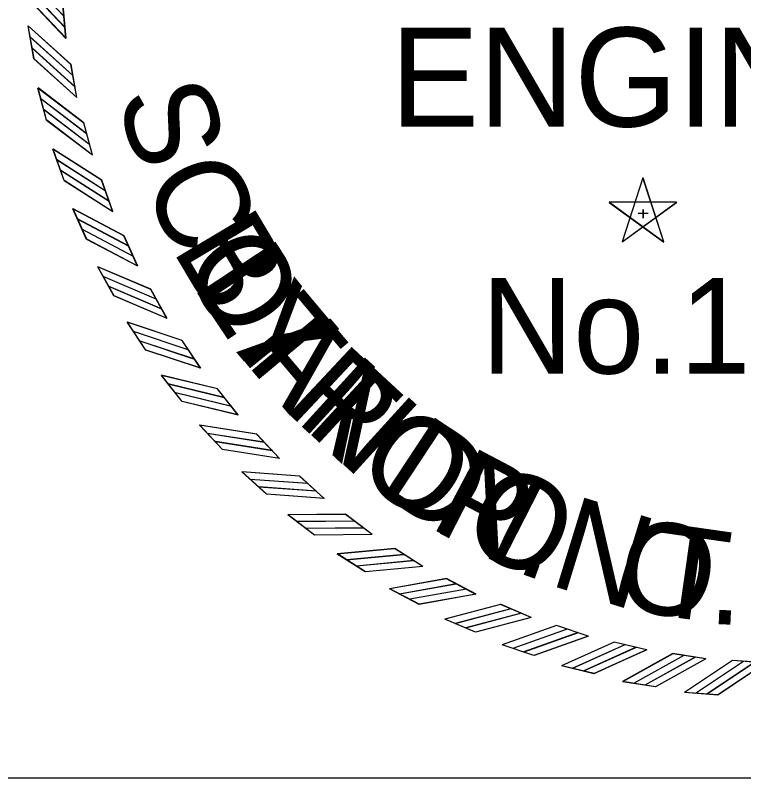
# Model space of a CAD drawing. Extents: x 0 to 1228740, y 0 to 152440.
# Drawn here: x 30.801 to 31.99, y 17.405 to 18.649 of the extents above; entities that cross this region are included whole.
import ezdxf

# ---------------------------------------------------------------- set-up
doc = ezdxf.new("R2010")
doc.units = 0
for name, color, linetype in [('R_No Plot', 7, 'Continuous'), ('STAMP_BOL', 7, 'Continuous'), ('STAMP_LKM', 7, 'Continuous'), ('STAMP_SPT', 7, 'Continuous')]:
    doc.layers.add(name, color=color, linetype=linetype)

msp = doc.modelspace()

# ---------------------------------------------------------------- linework, layer by layer
at = {"layer": 'R_No Plot'}
msp.add_lwpolyline([(30.6665, 20.1432), (30.6665, 17.4052), (33.4231, 17.4052)], dxfattribs=at)
msp.add_lwpolyline([(30.6665, 20.1432), (30.6665, 17.4052), (33.4231, 17.4052)], dxfattribs=at)
at = {"layer": 'STAMP_BOL'}
for p, q in [((30.8835, 18.6116), (30.8785, 18.6659)), ((30.8312, 18.5784), (30.8218, 18.632)), ((30.9012, 18.5153), (30.8917, 18.569)), ((30.8518, 18.4779), (30.8379, 18.5305)), ((30.9267, 18.4208), (30.9128, 18.4736)), ((30.8805, 18.3795), (30.8624, 18.4308)), ((30.9599, 18.3288), (30.9417, 18.3802)), ((31.8254, 18.3839), (31.7914, 18.2794)), ((31.8594, 18.2795), (31.8255, 18.384)), ((31.8803, 18.344), (31.7705, 18.3441)), ((31.7706, 18.344), (31.8594, 18.2793)), ((31.7915, 18.2795), (31.8804, 18.344)), ((30.9173, 18.2837), (30.895, 18.3333)), ((31.8176, 18.3264), (31.8339, 18.3264)), ((31.8255, 18.3323), (31.8255, 18.3185)), ((31.0006, 18.2397), (30.9782, 18.2895)), ((30.9619, 18.1913), (30.9356, 18.2389)), ((31.0485, 18.1544), (31.0221, 18.2021)), ((31.014, 18.103), (30.9838, 18.1482)), ((31.1033, 18.0733), (31.0731, 18.1187)), ((31.0731, 18.0192), (31.0393, 18.0618)), ((31.1647, 17.997), (31.1308, 18.0397)), ((31.139, 17.9406), (31.1018, 17.9803)), ((31.2321, 17.926), (31.1948, 17.9658)), ((31.2112, 17.8677), (31.1708, 17.9042)), ((31.3051, 17.8609), (31.2646, 17.8974)), ((31.2891, 17.801), (31.2459, 17.834)), ((31.3833, 17.8019), (31.3399, 17.835)), ((31.466, 17.7497), (31.4201, 17.7791)), ((31.3723, 17.741), (31.3265, 17.7703)), ((31.5528, 17.7044), (31.5046, 17.73)), ((31.4601, 17.688), (31.412, 17.7135)), ((31.6431, 17.6665), (31.5929, 17.688)), ((31.552, 17.6425), (31.502, 17.6639)), ((31.7361, 17.6362), (31.6844, 17.6534)), ((31.6474, 17.6047), (31.5958, 17.6219)), ((31.8314, 17.6137), (31.7784, 17.6266)), ((31.9282, 17.599), (31.8743, 17.6075)), ((32.0259, 17.5925), (31.9715, 17.5965)), ((31.7456, 17.575), (31.6927, 17.5878)), ((31.8458, 17.5534), (31.7921, 17.5619)), ((31.9475, 17.5402), (31.8933, 17.5442))]:
    msp.add_line(p, q, dxfattribs=at)
for points in [[(30.88, 18.6478), (30.8155, 18.7164)], [(30.8822, 18.629), (30.8177, 18.6976)], [(30.8836, 18.6116), (30.8191, 18.6802)], [(30.8917, 18.569), (30.8217, 18.632)], [(30.8946, 18.5511), (30.8247, 18.6141)], [(30.8983, 18.5325), (30.8284, 18.5956)], [(30.9012, 18.5153), (30.8313, 18.5783)], [(30.9128, 18.4735), (30.8379, 18.5306)], [(30.9172, 18.4559), (30.8423, 18.513)], [(30.9224, 18.4378), (30.8476, 18.4948)], [(30.9267, 18.4208), (30.8518, 18.4778)], [(30.9417, 18.3801), (30.8624, 18.4308)], [(30.9476, 18.363), (30.8682, 18.4136)], [(30.9543, 18.3453), (30.8749, 18.396)], [(30.96, 18.3287), (30.8806, 18.3794)], [(30.9782, 18.2894), (30.895, 18.3334)], [(30.9855, 18.2728), (30.9023, 18.3168)], [(30.9936, 18.2557), (30.9104, 18.2997)], [(31.0007, 18.2397), (30.9174, 18.2837)], [(31.0221, 18.202), (30.9355, 18.239)], [(31.0308, 18.1861), (30.9442, 18.223)], [(31.0403, 18.1698), (30.9537, 18.2067)], [(31.0486, 18.1544), (30.962, 18.1913)], [(31.0731, 18.1186), (30.9837, 18.1483)], [(31.083, 18.1034), (30.9936, 18.1331)], [(31.0938, 18.0879), (31.0045, 18.1176)], [(31.1034, 18.0733), (31.0141, 18.1029)], [(31.1308, 18.0396), (31.0393, 18.0618)], [(31.1419, 18.0253), (31.0504, 18.0475)], [(31.154, 18.0108), (31.0625, 18.033)], [(31.1647, 17.997), (31.0732, 18.0192)], [(31.1948, 17.9657), (31.1018, 17.9803)], [(31.207, 17.9524), (31.114, 17.9669)], [(31.2203, 17.9389), (31.1273, 17.9534)], [(31.2321, 17.926), (31.1391, 17.9406)], [(31.2647, 17.8973), (31.1708, 17.9042)], [(31.278, 17.8851), (31.1841, 17.8919)], [(31.2923, 17.8727), (31.1984, 17.8795)], [(31.3052, 17.8608), (31.2113, 17.8677)], [(31.34, 17.835), (31.2458, 17.834)], [(31.3543, 17.8238), (31.2601, 17.8229)], [(31.3695, 17.8127), (31.2754, 17.8117)], [(31.3834, 17.8019), (31.2892, 17.801)], [(31.4201, 17.779), (31.3264, 17.7703)], [(31.4353, 17.7691), (31.3416, 17.7604)], [(31.4515, 17.7593), (31.3577, 17.7505)], [(31.4661, 17.7497), (31.3724, 17.741)], [(31.5047, 17.7299), (31.412, 17.7135)], [(31.5206, 17.7213), (31.4279, 17.7048)], [(31.5375, 17.7128), (31.4448, 17.6964)], [(31.5529, 17.7045), (31.4602, 17.688)], [(31.593, 17.6879), (31.502, 17.6639)], [(31.6096, 17.6806), (31.5186, 17.6566)], [(31.6271, 17.6736), (31.5361, 17.6495)], [(31.6432, 17.6666), (31.5521, 17.6425)], [(31.6845, 17.6534), (31.5957, 17.6219)], [(31.7016, 17.6475), (31.6129, 17.616)], [(31.7197, 17.6419), (31.6309, 17.6104)], [(31.7362, 17.6362), (31.6475, 17.6047)], [(31.7785, 17.6265), (31.6926, 17.5878)], [(31.796, 17.622), (31.7102, 17.5834)], [(31.8145, 17.618), (31.7287, 17.5793)], [(31.8315, 17.6137), (31.7456, 17.575)], [(31.8744, 17.6075), (31.792, 17.5618)], [(31.8923, 17.6045), (31.8099, 17.5588)], [(31.911, 17.602), (31.8286, 17.5563)], [(31.9283, 17.5991), (31.8459, 17.5534)], [(31.9715, 17.5964), (31.8932, 17.5442)], [(31.9896, 17.5949), (31.9113, 17.5427)], [(32.0085, 17.594), (31.9302, 17.5417)], [(32.0259, 17.5925), (31.9476, 17.5402)]]:
    msp.add_lwpolyline(points, dxfattribs=at)
at = {"layer": 'STAMP_LKM'}
for p, q in [((30.8838, 18.6117), (30.8788, 18.666)), ((30.8315, 18.5785), (30.822, 18.6321)), ((30.9014, 18.5154), (30.8919, 18.5691)), ((30.852, 18.478), (30.8382, 18.5306)), ((30.9269, 18.4209), (30.913, 18.4737)), ((30.8808, 18.3796), (30.8626, 18.4309)), ((30.9601, 18.3289), (30.9419, 18.3803)), ((31.8256, 18.384), (31.7915, 18.2795)), ((31.8595, 18.2796), (31.8257, 18.3841)), ((31.8805, 18.3441), (31.7706, 18.3442)), ((31.7707, 18.3441), (31.8595, 18.2795)), ((31.7917, 18.2796), (31.8806, 18.3441)), ((30.9176, 18.2838), (30.8953, 18.3335)), ((31.8178, 18.3266), (31.8341, 18.3266)), ((31.8257, 18.3324), (31.8257, 18.3186)), ((31.0008, 18.2399), (30.9785, 18.2896)), ((30.9621, 18.1915), (30.9358, 18.2391)), ((31.0487, 18.1545), (31.0223, 18.2022)), ((31.0142, 18.1031), (30.984, 18.1484)), ((31.1035, 18.0734), (31.0733, 18.1188)), ((31.0734, 18.0193), (31.0395, 18.0619)), ((31.1649, 17.9971), (31.131, 18.0399)), ((31.1392, 17.9407), (31.102, 17.9804)), ((31.2323, 17.9262), (31.195, 17.9659)), ((31.2114, 17.8678), (31.171, 17.9043)), ((31.3053, 17.861), (31.2648, 17.8976)), ((31.2893, 17.8012), (31.2461, 17.8342)), ((31.3835, 17.8021), (31.3401, 17.8352)), ((31.4662, 17.7499), (31.4203, 17.7793)), ((31.3725, 17.7411), (31.3267, 17.7705)), ((31.553, 17.7046), (31.5048, 17.7301)), ((31.4603, 17.6882), (31.4122, 17.7136)), ((31.6432, 17.6667), (31.5931, 17.6881)), ((31.5522, 17.6427), (31.5022, 17.6641)), ((31.7363, 17.6364), (31.6846, 17.6536)), ((31.6476, 17.6049), (31.5959, 17.6221)), ((31.8315, 17.6138), (31.7786, 17.6267)), ((31.9283, 17.5992), (31.8745, 17.6077)), ((32.026, 17.5927), (31.9716, 17.5967)), ((31.7457, 17.5751), (31.6929, 17.588)), ((31.846, 17.5536), (31.7922, 17.562)), ((31.9477, 17.5404), (31.8934, 17.5444))]:
    msp.add_line(p, q, dxfattribs=at)
for points in [[(30.8802, 18.6479), (30.8158, 18.7165)], [(30.8824, 18.6291), (30.8179, 18.6977)], [(30.8838, 18.6116), (30.8194, 18.6803)], [(30.8919, 18.5691), (30.822, 18.6321)], [(30.8949, 18.5512), (30.825, 18.6142)], [(30.8986, 18.5326), (30.8287, 18.5957)], [(30.9014, 18.5154), (30.8315, 18.5784)], [(30.913, 18.4736), (30.8381, 18.5307)], [(30.9174, 18.456), (30.8426, 18.5131)], [(30.9227, 18.4379), (30.8478, 18.4949)], [(30.927, 18.4209), (30.8521, 18.4779)], [(30.9419, 18.3802), (30.8626, 18.4309)], [(30.9478, 18.3631), (30.8685, 18.4137)], [(30.9545, 18.3454), (30.8752, 18.3961)], [(30.9602, 18.3288), (30.8808, 18.3795)], [(30.9784, 18.2895), (30.8952, 18.3335)], [(30.9857, 18.2729), (30.9025, 18.3169)], [(30.9939, 18.2559), (30.9106, 18.2998)], [(31.0009, 18.2398), (30.9176, 18.2838)], [(31.0223, 18.2022), (30.9357, 18.2391)], [(31.031, 18.1862), (30.9444, 18.2232)], [(31.0405, 18.1699), (30.9539, 18.2068)], [(31.0488, 18.1545), (30.9622, 18.1914)], [(31.0733, 18.1187), (30.984, 18.1484)], [(31.0832, 18.1036), (30.9939, 18.1332)], [(31.094, 18.0881), (31.0047, 18.1177)], [(31.1036, 18.0734), (31.0143, 18.1031)], [(31.131, 18.0398), (31.0395, 18.062)], [(31.1421, 18.0255), (31.0506, 18.0477)], [(31.1542, 18.0109), (31.0627, 18.0331)], [(31.1649, 17.9971), (31.0734, 18.0193)], [(31.195, 17.9659), (31.102, 17.9804)], [(31.2072, 17.9525), (31.1142, 17.9671)], [(31.2205, 17.939), (31.1275, 17.9536)], [(31.2323, 17.9262), (31.1393, 17.9407)], [(31.2649, 17.8975), (31.171, 17.9043)], [(31.2782, 17.8852), (31.1843, 17.892)], [(31.2925, 17.8729), (31.1986, 17.8797)], [(31.3054, 17.861), (31.2115, 17.8678)], [(31.3401, 17.8351), (31.246, 17.8342)], [(31.3544, 17.824), (31.2603, 17.823)], [(31.3697, 17.8129), (31.2756, 17.8119)], [(31.3835, 17.8021), (31.2894, 17.8011)], [(31.4203, 17.7792), (31.3266, 17.7705)], [(31.4355, 17.7693), (31.3418, 17.7605)], [(31.4516, 17.7594), (31.3579, 17.7507)], [(31.4663, 17.7499), (31.3726, 17.7411)], [(31.5049, 17.7301), (31.4122, 17.7136)], [(31.5208, 17.7214), (31.4281, 17.705)], [(31.5377, 17.713), (31.445, 17.6965)], [(31.5531, 17.7046), (31.4604, 17.6882)], [(31.5932, 17.6881), (31.5021, 17.664)], [(31.6098, 17.6808), (31.5187, 17.6568)], [(31.6273, 17.6738), (31.5363, 17.6497)], [(31.6433, 17.6667), (31.5523, 17.6427)], [(31.6846, 17.6535), (31.5959, 17.6221)], [(31.7018, 17.6477), (31.613, 17.6162)], [(31.7198, 17.6421), (31.6311, 17.6106)], [(31.7364, 17.6364), (31.6477, 17.6049)], [(31.7786, 17.6267), (31.6928, 17.588)], [(31.7962, 17.6222), (31.7104, 17.5835)], [(31.8146, 17.6182), (31.7288, 17.5795)], [(31.8316, 17.6139), (31.7458, 17.5752)], [(31.8745, 17.6077), (31.7922, 17.562)], [(31.8924, 17.6047), (31.8101, 17.559)], [(31.9111, 17.6021), (31.8288, 17.5565)], [(31.9284, 17.5993), (31.8461, 17.5536)], [(31.9717, 17.5966), (31.8934, 17.5443)], [(31.9897, 17.5951), (31.9114, 17.5428)], [(32.0086, 17.5942), (31.9303, 17.5419)], [(32.0261, 17.5927), (31.9478, 17.5404)]]:
    msp.add_lwpolyline(points, dxfattribs=at)
at = {"layer": 'STAMP_SPT'}
for p, q in [((30.8837, 18.6117), (30.8787, 18.666)), ((30.8314, 18.5785), (30.822, 18.6321)), ((30.9013, 18.5154), (30.8918, 18.5691)), ((30.8519, 18.478), (30.8381, 18.5306)), ((30.9268, 18.4209), (30.9129, 18.4737)), ((30.8807, 18.3796), (30.8626, 18.4309)), ((30.96, 18.3289), (30.9419, 18.3803)), ((31.8255, 18.384), (31.7915, 18.2795)), ((31.8594, 18.2796), (31.8256, 18.3841)), ((31.8804, 18.3441), (31.7705, 18.3442)), ((31.7706, 18.3441), (31.8594, 18.2795)), ((31.7916, 18.2796), (31.8805, 18.3441)), ((30.9175, 18.2838), (30.8952, 18.3335)), ((31.8177, 18.3266), (31.834, 18.3266)), ((31.8256, 18.3324), (31.8256, 18.3186)), ((31.0007, 18.2399), (30.9784, 18.2896)), ((30.9621, 18.1915), (30.9357, 18.2391)), ((31.0487, 18.1545), (31.0223, 18.2022)), ((31.0141, 18.1031), (30.9839, 18.1484)), ((31.1035, 18.0734), (31.0732, 18.1188)), ((31.0733, 18.0193), (31.0395, 18.062)), ((31.1648, 17.9971), (31.1309, 18.0399)), ((31.1392, 17.9407), (31.1019, 17.9804)), ((31.2322, 17.9262), (31.1949, 17.966)), ((31.2113, 17.8678), (31.1709, 17.9043)), ((31.3052, 17.861), (31.2648, 17.8976)), ((31.2892, 17.8012), (31.246, 17.8342)), ((31.3834, 17.8021), (31.34, 17.8352)), ((31.4661, 17.7499), (31.4202, 17.7793)), ((31.3724, 17.7411), (31.3266, 17.7705)), ((31.5529, 17.7046), (31.5047, 17.7301)), ((31.4602, 17.6882), (31.4121, 17.7136)), ((31.6432, 17.6667), (31.593, 17.6882)), ((31.5521, 17.6427), (31.5021, 17.6641)), ((31.7362, 17.6364), (31.6845, 17.6536)), ((31.6475, 17.6049), (31.5959, 17.6221)), ((31.8315, 17.6138), (31.7785, 17.6267)), ((31.9283, 17.5992), (31.8744, 17.6077)), ((32.0259, 17.5927), (31.9715, 17.5967)), ((31.7456, 17.5751), (31.6928, 17.588)), ((31.8459, 17.5536), (31.7922, 17.5621)), ((31.9476, 17.5404), (31.8934, 17.5444))]:
    msp.add_line(p, q, dxfattribs=at)
for points in [[(30.8802, 18.6479), (30.8157, 18.7165)], [(30.8823, 18.6291), (30.8178, 18.6977)], [(30.8838, 18.6117), (30.8193, 18.6803)], [(30.8918, 18.5691), (30.8219, 18.6321)], [(30.8948, 18.5512), (30.8249, 18.6142)], [(30.8985, 18.5327), (30.8286, 18.5957)], [(30.9014, 18.5154), (30.8315, 18.5784)], [(30.9129, 18.4736), (30.838, 18.5307)], [(30.9174, 18.456), (30.8425, 18.5131)], [(30.9226, 18.4379), (30.8477, 18.4949)], [(30.9269, 18.4209), (30.852, 18.478)], [(30.9418, 18.3802), (30.8625, 18.4309)], [(30.9477, 18.3631), (30.8684, 18.4138)], [(30.9544, 18.3454), (30.8751, 18.3961)], [(30.9601, 18.3288), (30.8808, 18.3795)], [(30.9784, 18.2895), (30.8951, 18.3335)], [(30.9857, 18.2729), (30.9024, 18.3169)], [(30.9938, 18.2559), (30.9105, 18.2998)], [(31.0008, 18.2398), (30.9176, 18.2838)], [(31.0223, 18.2022), (30.9357, 18.2391)], [(31.0309, 18.1862), (30.9443, 18.2232)], [(31.0404, 18.1699), (30.9538, 18.2068)], [(31.0487, 18.1545), (30.9621, 18.1914)], [(31.0732, 18.1187), (30.9839, 18.1484)], [(31.0831, 18.1036), (30.9938, 18.1332)], [(31.094, 18.0881), (31.0046, 18.1177)], [(31.1035, 18.0734), (31.0142, 18.1031)], [(31.1309, 18.0398), (31.0394, 18.062)], [(31.142, 18.0255), (31.0505, 18.0477)], [(31.1541, 18.0109), (31.0626, 18.0331)], [(31.1649, 17.9971), (31.0734, 18.0193)], [(31.1949, 17.9659), (31.1019, 17.9804)], [(31.2072, 17.9526), (31.1142, 17.9671)], [(31.2204, 17.939), (31.1274, 17.9536)], [(31.2323, 17.9262), (31.1393, 17.9407)], [(31.2648, 17.8975), (31.1709, 17.9043)], [(31.2781, 17.8852), (31.1842, 17.8921)], [(31.2924, 17.8729), (31.1985, 17.8797)], [(31.3053, 17.861), (31.2114, 17.8678)], [(31.3401, 17.8351), (31.2459, 17.8342)], [(31.3544, 17.824), (31.2602, 17.8231)], [(31.3696, 17.8129), (31.2755, 17.8119)], [(31.3835, 17.8021), (31.2893, 17.8012)], [(31.4203, 17.7792), (31.3265, 17.7705)], [(31.4354, 17.7693), (31.3417, 17.7606)], [(31.4516, 17.7595), (31.3578, 17.7507)], [(31.4662, 17.7499), (31.3725, 17.7411)], [(31.5048, 17.7301), (31.4121, 17.7136)], [(31.5207, 17.7215), (31.428, 17.705)], [(31.5376, 17.713), (31.4449, 17.6965)], [(31.553, 17.7046), (31.4603, 17.6882)], [(31.5931, 17.6881), (31.5021, 17.6641)], [(31.6097, 17.6808), (31.5187, 17.6568)], [(31.6272, 17.6738), (31.5362, 17.6497)], [(31.6433, 17.6667), (31.5522, 17.6427)], [(31.6845, 17.6536), (31.5958, 17.6221)], [(31.7017, 17.6477), (31.613, 17.6162)], [(31.7197, 17.6421), (31.631, 17.6106)], [(31.7363, 17.6364), (31.6476, 17.6049)], [(31.7785, 17.6267), (31.6927, 17.588)], [(31.7961, 17.6222), (31.7103, 17.5835)], [(31.8146, 17.6182), (31.7288, 17.5795)], [(31.8315, 17.6139), (31.7457, 17.5752)], [(31.8744, 17.6077), (31.7921, 17.562)], [(31.8923, 17.6047), (31.81, 17.559)], [(31.9111, 17.6022), (31.8287, 17.5565)], [(31.9283, 17.5993), (31.846, 17.5536)], [(31.9716, 17.5966), (31.8933, 17.5443)], [(31.9896, 17.5951), (31.9114, 17.5428)], [(32.0085, 17.5942), (31.9302, 17.5419)], [(32.026, 17.5927), (31.9477, 17.5404)]]:
    msp.add_lwpolyline(points, dxfattribs=at)

# ---------------------------------------------------------------- texts
at = {"layer": 'STAMP_BOL'}
for s, height, p in [('ENGINEER', 0.16156, (31.4136, 18.4676)), ('No.13640', 0.15579, (31.5613, 18.0647))]:
    msp.add_text(s, height=height, dxfattribs=at).set_placement(p)
for s, rotation, p in [('B', 300.7985, (31.0554, 18.2682)), ('Y', 308.8241, (31.1362, 18.1327)), ('R', 316.8497, (31.2352, 18.0098)), ('O', 324.8753, (31.3503, 17.9019)), ('N', 332.9009, (31.4793, 17.8111)), ('O', 349.3169, (31.7758, 17.6859)), ('.', 357.3425, (31.9308, 17.6567))]:
    msp.add_text(s, height=0.1503, rotation=rotation, dxfattribs=at).set_placement(p)
at = {"layer": 'STAMP_LKM'}
for s, height, p in [('ENGINEER', 0.16155, (31.4137, 18.4677)), ('No.18633', 0.15578, (31.5614, 18.0649))]:
    msp.add_text(s, height=height, dxfattribs=at).set_placement(p)
for s, rotation, p in [('L', 303.5658, (31.0886, 18.2093)), ('A', 310.2488, (31.1612, 18.0999)), ('N', 317.6744, (31.2562, 17.9892)), ('D', 326.585, (31.3878, 17.874)), ('O', 334.7531, (31.5229, 17.7874)), ('N', 342.9212, (31.6689, 17.7208))]:
    msp.add_text(s, height=0.153, rotation=rotation, dxfattribs=at).set_placement(p)
at = {"layer": 'STAMP_SPT'}
for s, height, p in [('ENGINEER', 0.16155, (31.4137, 18.4677)), ('No.10887', 0.15578, (31.5614, 18.0649))]:
    msp.add_text(s, height=height, dxfattribs=at).set_placement(p)
for s, rotation, p in [('S', 286.9475, (30.9653, 18.5171)), ('C', 294.2435, (31.0071, 18.3799)), ('O', 301.9044, (31.0694, 18.2429)), ('T', 309.93, (31.1536, 18.1096)), ('T', 317.226, (31.2456, 17.9997)), ('P', 332.1828, (31.4737, 17.8153)), ('T', 351.882, (31.832, 17.6734)), ('.', 340.2084, (31.6136, 17.7427))]:
    msp.add_text(s, height=0.1503, rotation=rotation, dxfattribs=at).set_placement(p)

doc.saveas('drawing.dxf')
